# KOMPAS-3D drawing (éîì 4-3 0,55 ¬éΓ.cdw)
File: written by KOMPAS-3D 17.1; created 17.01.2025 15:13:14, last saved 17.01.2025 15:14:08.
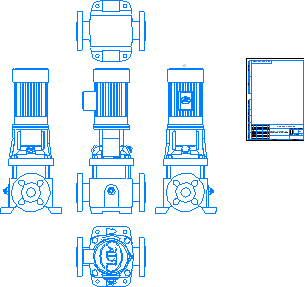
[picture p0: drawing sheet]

Sheet 1: A4, portrait

Title block, sheet 1: name: ВМН 4-3 0,55 кВт; designation: ВМН 4-3 0,55 кВт; sheets: 1; sheet format: A4; stored path: \\adlc.lan\data\АДЛ_ПКД\3D-модели\ADL production\Насосы ГРАНПАМП\Насосы ВМН\ВМН4\KOMPAS 2D\ВМН 4-3 0,55 кВт.cdw

Views: Проекционный вид 2, Проекционный вид 3, Проекционный вид 4, Проекционный вид 5
Referenced files in \\adlc.lan\data\АДЛ_ПКД\3D-модели\ADL production\Насосы ГРАНПАМП\Насосы ВМН\ВМН4\KOMPAS 3D\: ВМН 4-3 0,55 кВт.m3d
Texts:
  Andrey
  АДЛ
Dimensions and other numbers on the sheet: 1:1; 1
